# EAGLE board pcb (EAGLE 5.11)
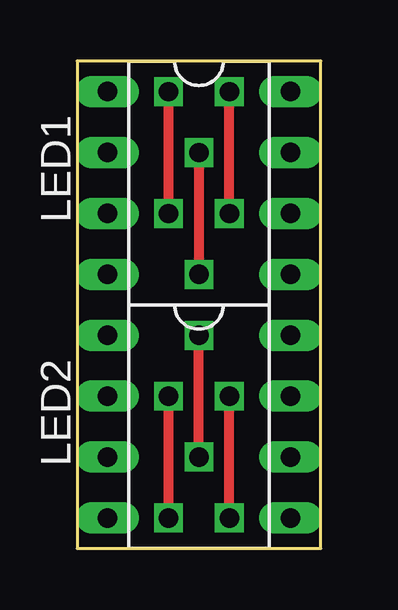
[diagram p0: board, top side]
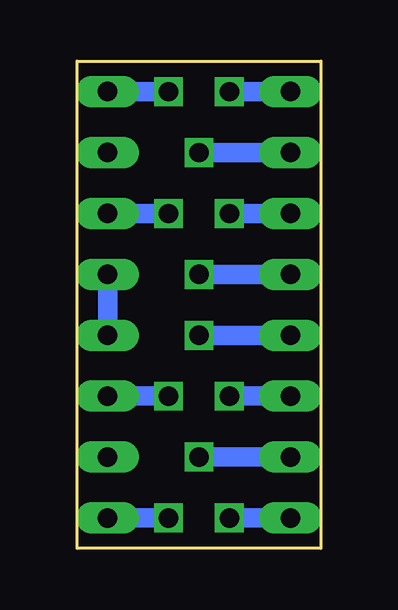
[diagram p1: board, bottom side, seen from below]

Size 10.16 x 20.32 mm. Coordinates in mm from the lower left corner, seen from the top.
Outline: 0,0 10.16,0 10.16,20.32 0,20.32 0,0
Copper layers (1*16): Top 0.035mm / dielectric 1.5mm / Bottom 0.035mm
Design rules "default": minimum track width 10mil, minimum drill 24mil, track to track 8mil, track to pad 8mil, pad to pad 8mil, via to via 8mil, smd to smd 8mil, copper to edge 40mil, drill to drill 8mil, minimum pad ring 10mil, minimum via ring 8mil, stop-mask expansion 4mil, vias tented up to drill 0mil, thermal gap 10mil

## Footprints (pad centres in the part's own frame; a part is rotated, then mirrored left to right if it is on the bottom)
DIL08 = drill 0.813 long: 1 -3.81,-3.81; 2 -1.27,-3.81; 3 1.27,-3.81; 4 3.81,-3.81; 5 3.81,3.81; 6 1.27,3.81; 7 -1.27,3.81; 8 -3.81,3.81

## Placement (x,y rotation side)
LED1  HLMP 2x55  [DIL08]  5.08,15.24 270 top
LED2  HLMP 2x55  [DIL08]  5.08,5.08 270 top

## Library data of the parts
LED1 LED2 = 40xx

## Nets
S$1: LED1.2 LED1.4
S$2: LED1.5 LED2.8
S$4: LED1.1 LED1.3
S$5: LED1.6 LED1.8
S$8: LED2.2 LED2.4
S$10: LED2.5 LED2.7
S$11: LED2.1 LED2.3

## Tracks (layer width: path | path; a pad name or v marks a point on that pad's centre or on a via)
S$1  (via drill 0.8)
  Top 0.406: v5.08,16.51 v5.08,11.43
  Bottom 0.813: LED1.2 v5.08,16.51 | LED1.4 v5.08,11.43
S$2
  Bottom 0.813: LED1.5 LED2.8
S$4  (via drill 0.8)
  Top 0.406: v3.81,13.97 v3.81,19.05
  Bottom 0.813: LED1.3 v3.81,13.97 | LED1.1 v3.81,19.05
S$5  (via drill 0.8)
  Top 0.406: v6.35,13.97 v6.35,19.05
  Bottom 0.813: LED1.6 v6.35,13.97 | LED1.8 v6.35,19.05
S$8  (via drill 0.8)
  Top 0.406: v3.81,1.27 v3.81,6.35
  Bottom 0.813: LED2.4 v3.81,1.27 | LED2.2 v3.81,6.35
S$10  (via drill 0.8)
  Top 0.406: v6.35,1.27 v6.35,6.35
  Bottom 0.813: LED2.5 v6.35,1.27 | LED2.7 v6.35,6.35
S$11  (via drill 0.8)
  Top 0.406: v5.08,3.81 v5.08,8.89
  Bottom 0.813: LED2.3 v5.08,3.81 | LED2.1 v5.08,8.89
